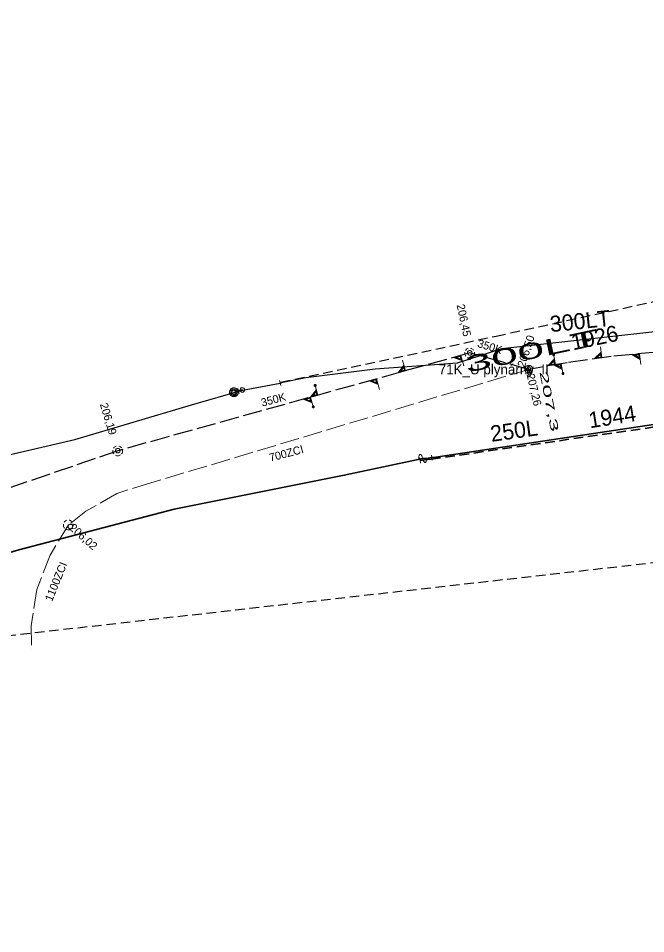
# Model space of a CAD drawing. Extents: x -740786 to -740000, y -1046854 to -1046100.
# Drawn here: x -740571.3 to -740508.6, y -1046832.5 to -1046741 of the extents above; entities that cross this region are included whole.
import ezdxf

# ---------------------------------------------------------------- set-up
doc = ezdxf.new("R2010")
doc.units = 0
doc.header["$LTSCALE"] = 0.32
doc.linetypes.add('LONG_DASHED', pattern=[7.5, 6, -1.5])
doc.linetypes.add('MEDIUM_DASHED', pattern=[4.5, 3, -1.5])
doc.layers.add('1', color=7, linetype='Continuous')
doc.layers.add('15', color=7, linetype='Continuous')
for name, color, linetype, lineweight in [('18', 7, 'Continuous', 13), ('20', 7, 'LONG_DASHED', 25), ('63', 7, 'MEDIUM_DASHED', 25), ('8', 7, 'Continuous', 13)]:
    doc.layers.add(name, color=color, linetype=linetype, lineweight=lineweight)

msp = doc.modelspace()

# ---------------------------------------------------------------- linework, layer by layer
at = {"layer": '18'}
for points in [[(-740526.323, -1046773.977), (-740526.394, -1046774.005), (-740526.461, -1046774.044), (-740526.521, -1046774.092), (-740526.572, -1046774.149), (-740526.596, -1046774.183)], [(-740525.782, -1046774.16), (-740525.832, -1046774.102), (-740525.89, -1046774.052), (-740525.955, -1046774.011), (-740526.026, -1046773.982), (-740526.075, -1046773.968)], [(-740513.109, -1046773.844), (-740512.959, -1046774.93), (-740513.722, -1046775.035), (-740513.039, -1046774.357)], [(-740526.76, -1046775.738), (-740527.054, -1046774.682), (-740527.797, -1046774.889), (-740526.899, -1046775.239)], [(-740526.98, -1046775.139), (-740527.091, -1046774.738), (-740527.636, -1046774.89), (-740526.98, -1046775.14)], [(-740527.048, -1046775.071), (-740527.126, -1046774.79), (-740527.483, -1046774.89), (-740527.047, -1046775.07)], [(-740526.668, -1046774.369), (-740526.674, -1046774.446), (-740526.669, -1046774.523), (-740526.652, -1046774.598), (-740526.623, -1046774.669), (-740526.583, -1046774.735), (-740526.567, -1046774.757)], [(-740526.41, -1046774.886), (-740526.34, -1046774.917), (-740526.265, -1046774.936), (-740526.189, -1046774.943), (-740526.112, -1046774.938), (-740526.037, -1046774.921), (-740525.965, -1046774.893), (-740525.905, -1046774.858)], [(-740525.787, -1046774.746), (-740525.746, -1046774.681), (-740525.715, -1046774.611), (-740525.696, -1046774.536), (-740525.688, -1046774.46), (-740525.693, -1046774.383), (-740525.699, -1046774.348)], [(-740517.798, -1046774.531), (-740517.609, -1046775.61), (-740518.368, -1046775.742), (-740517.709, -1046775.041)], [(-740513.072, -1046774.481), (-740513.015, -1046774.893), (-740513.576, -1046774.971), (-740513.072, -1046774.48)], [(-740513.107, -1046774.571), (-740513.067, -1046774.859), (-740513.436, -1046774.91), (-740513.106, -1046774.571)], [(-740509.079, -1046775.608), (-740509.187, -1046774.517), (-740509.954, -1046774.593), (-740509.13, -1046775.093)], [(-740509.192, -1046774.98), (-740509.233, -1046774.566), (-740509.795, -1046774.622), (-740509.192, -1046774.981)], [(-740509.247, -1046774.901), (-740509.276, -1046774.612), (-740509.645, -1046774.648), (-740509.246, -1046774.901)], [(-740532.883, -1046775.168), (-740532.589, -1046776.224), (-740533.331, -1046776.43), (-740532.744, -1046775.667)], [(-740532.761, -1046775.794), (-740532.649, -1046776.195), (-740533.195, -1046776.347), (-740532.761, -1046775.793)], [(-740532.784, -1046775.888), (-740532.706, -1046776.168), (-740533.064, -1046776.268), (-740532.783, -1046775.887)], [(-740517.738, -1046775.165), (-740517.666, -1046775.575), (-740518.224, -1046775.673), (-740517.738, -1046775.164)], [(-740517.77, -1046775.256), (-740517.719, -1046775.544), (-740518.086, -1046775.608), (-740517.769, -1046775.256)], [(-740516.831, -1046776.592), (-740517.019, -1046775.513), (-740517.779, -1046775.646), (-740516.92, -1046776.083)], [(-740516.99, -1046775.974), (-740517.062, -1046775.564), (-740517.62, -1046775.662), (-740516.99, -1046775.976)], [(-740517.051, -1046775.9), (-740517.101, -1046775.613), (-740517.467, -1046775.677), (-740517.05, -1046775.9)], [(-740541.641, -1046777.599), (-740541.348, -1046778.654), (-740542.09, -1046778.86), (-740541.503, -1046778.097)], [(-740535.19, -1046778.082), (-740535.484, -1046777.026), (-740536.227, -1046777.233), (-740535.329, -1046777.583)], [(-740535.41, -1046777.483), (-740535.521, -1046777.082), (-740536.066, -1046777.234), (-740535.41, -1046777.484)], [(-740535.478, -1046777.415), (-740535.556, -1046777.134), (-740535.913, -1046777.234), (-740535.477, -1046777.414)], [(-740541.519, -1046778.224), (-740541.408, -1046778.625), (-740541.953, -1046778.776), (-740541.519, -1046778.223)], [(-740541.542, -1046778.318), (-740541.464, -1046778.599), (-740541.822, -1046778.699), (-740541.541, -1046778.317)], [(-740541.787, -1046779.919), (-740542.08, -1046778.864), (-740542.823, -1046779.071), (-740541.925, -1046779.421)], [(-740542.006, -1046779.32), (-740542.118, -1046778.919), (-740542.663, -1046779.071), (-740542.006, -1046779.322)], [(-740542.074, -1046779.253), (-740542.152, -1046778.971), (-740542.509, -1046779.071), (-740542.073, -1046779.252)], [(-740561.848, -1046784.149), (-740561.853, -1046784.226), (-740561.848, -1046784.303), (-740561.831, -1046784.378), (-740561.803, -1046784.449), (-740561.762, -1046784.515), (-740561.747, -1046784.537)], [(-740561.503, -1046783.757), (-740561.574, -1046783.785), (-740561.641, -1046783.824), (-740561.701, -1046783.872), (-740561.752, -1046783.929), (-740561.776, -1046783.963)], [(-740560.962, -1046783.94), (-740561.012, -1046783.882), (-740561.07, -1046783.832), (-740561.135, -1046783.791), (-740561.206, -1046783.762), (-740561.255, -1046783.748)], [(-740560.967, -1046784.526), (-740560.926, -1046784.461), (-740560.895, -1046784.391), (-740560.875, -1046784.316), (-740560.868, -1046784.24), (-740560.873, -1046784.163), (-740560.879, -1046784.128)], [(-740561.59, -1046784.666), (-740561.52, -1046784.697), (-740561.445, -1046784.716), (-740561.369, -1046784.723), (-740561.292, -1046784.718), (-740561.217, -1046784.701), (-740561.145, -1046784.673), (-740561.085, -1046784.638)], [(-740566.442, -1046791.167), (-740566.513, -1046791.195), (-740566.58, -1046791.234), (-740566.64, -1046791.282), (-740566.691, -1046791.339), (-740566.715, -1046791.373)], [(-740565.901, -1046791.35), (-740565.951, -1046791.292), (-740566.009, -1046791.242), (-740566.074, -1046791.201), (-740566.145, -1046791.172), (-740566.194, -1046791.158)], [(-740566.787, -1046791.559), (-740566.793, -1046791.636), (-740566.788, -1046791.713), (-740566.771, -1046791.788), (-740566.742, -1046791.859), (-740566.701, -1046791.925), (-740566.686, -1046791.947)], [(-740566.529, -1046792.076), (-740566.459, -1046792.107), (-740566.384, -1046792.126), (-740566.308, -1046792.133), (-740566.231, -1046792.128), (-740566.156, -1046792.111), (-740566.084, -1046792.083), (-740566.024, -1046792.048)], [(-740565.906, -1046791.936), (-740565.865, -1046791.871), (-740565.834, -1046791.801), (-740565.815, -1046791.726), (-740565.807, -1046791.65), (-740565.812, -1046791.573), (-740565.818, -1046791.538)]]:
    msp.add_lwpolyline(points, dxfattribs=at)
for points in [[(-740525.939, -1046774.429), (-740525.945, -1046774.377), (-740525.963, -1046774.327), (-740525.991, -1046774.283), (-740526.029, -1046774.246), (-740526.074, -1046774.219), (-740526.124, -1046774.203), (-740526.176, -1046774.198), (-740526.228, -1046774.205), (-740526.277, -1046774.224), (-740526.321, -1046774.254), (-740526.356, -1046774.293), (-740526.382, -1046774.338), (-740526.397, -1046774.389), (-740526.4, -1046774.441), (-740526.392, -1046774.493), (-740526.371, -1046774.541), (-740526.341, -1046774.584), (-740526.301, -1046774.619), (-740526.255, -1046774.643), (-740526.204, -1046774.657), (-740526.152, -1046774.659), (-740526.1, -1046774.649), (-740526.052, -1046774.627), (-740526.01, -1046774.595), (-740525.977, -1046774.555), (-740525.953, -1046774.508), (-740525.941, -1046774.457)], [(-740517.874, -1046774.64), (-740517.863, -1046774.671), (-740517.841, -1046774.697), (-740517.812, -1046774.713), (-740517.778, -1046774.718), (-740517.746, -1046774.711), (-740517.718, -1046774.693), (-740517.697, -1046774.666), (-740517.687, -1046774.634), (-740517.69, -1046774.601), (-740517.704, -1046774.571), (-740517.727, -1046774.546), (-740517.758, -1046774.532), (-740517.791, -1046774.53), (-740517.824, -1046774.539), (-740517.851, -1046774.559), (-740517.868, -1046774.587), (-740517.876, -1046774.62)], [(-740517.847, -1046774.636), (-740517.837, -1046774.663), (-740517.817, -1046774.683), (-740517.79, -1046774.691), (-740517.762, -1046774.689), (-740517.737, -1046774.676), (-740517.721, -1046774.653), (-740517.714, -1046774.625), (-740517.72, -1046774.598), (-740517.736, -1046774.575), (-740517.761, -1046774.561), (-740517.789, -1046774.558), (-740517.816, -1046774.567), (-740517.837, -1046774.587), (-740517.848, -1046774.612)], [(-740519.882, -1046776.076), (-740519.888, -1046776.008), (-740519.906, -1046775.941), (-740519.935, -1046775.879), (-740519.974, -1046775.822), (-740520.023, -1046775.773), (-740520.079, -1046775.734), (-740520.141, -1046775.705), (-740520.208, -1046775.686), (-740520.276, -1046775.68), (-740520.345, -1046775.686), (-740520.412, -1046775.703), (-740520.474, -1046775.732), (-740520.531, -1046775.771), (-740520.58, -1046775.82), (-740520.62, -1046775.876), (-740520.649, -1046775.938), (-740520.668, -1046776.005), (-740520.674, -1046776.073), (-740520.669, -1046776.142), (-740520.651, -1046776.209), (-740520.623, -1046776.271), (-740520.584, -1046776.328), (-740520.536, -1046776.377), (-740520.48, -1046776.417), (-740520.417, -1046776.447), (-740520.351, -1046776.466), (-740520.283, -1046776.472), (-740520.214, -1046776.467), (-740520.147, -1046776.45), (-740520.084, -1046776.422), (-740520.027, -1046776.383), (-740519.978, -1046776.335), (-740519.938, -1046776.279), (-740519.908, -1046776.217), (-740519.889, -1046776.151), (-740519.882, -1046776.082)], [(-740520.267, -1046776.377), (-740520.231, -1046776.371), (-740520.196, -1046776.353), (-740520.164, -1046776.324), (-740520.136, -1046776.285), (-740520.114, -1046776.238), (-740520.098, -1046776.185), (-740520.089, -1046776.127), (-740520.087, -1046776.068), (-740520.093, -1046776.009), (-740520.106, -1046775.954), (-740520.126, -1046775.903), (-740520.151, -1046775.86), (-740520.182, -1046775.826), (-740520.216, -1046775.802), (-740520.252, -1046775.789), (-740520.289, -1046775.789), (-740520.325, -1046775.8), (-740520.359, -1046775.823), (-740520.389, -1046775.857), (-740520.414, -1046775.899), (-740520.434, -1046775.949), (-740520.447, -1046776.005), (-740520.453, -1046776.063), (-740520.451, -1046776.123), (-740520.442, -1046776.181), (-740520.426, -1046776.234), (-740520.404, -1046776.282), (-740520.376, -1046776.321), (-740520.344, -1046776.351), (-740520.309, -1046776.37), (-740520.272, -1046776.377)], [(-740519.946, -1046776.393), (-740519.953, -1046776.341), (-740519.97, -1046776.291), (-740519.999, -1046776.247), (-740520.037, -1046776.21), (-740520.081, -1046776.183), (-740520.132, -1046776.167), (-740520.184, -1046776.162), (-740520.235, -1046776.169), (-740520.284, -1046776.188), (-740520.328, -1046776.218), (-740520.364, -1046776.257), (-740520.39, -1046776.302), (-740520.404, -1046776.353), (-740520.407, -1046776.405), (-740520.399, -1046776.457), (-740520.379, -1046776.505), (-740520.348, -1046776.548), (-740520.309, -1046776.583), (-740520.262, -1046776.607), (-740520.212, -1046776.621), (-740520.159, -1046776.623), (-740520.108, -1046776.613), (-740520.059, -1046776.591), (-740520.017, -1046776.559), (-740519.985, -1046776.519), (-740519.961, -1046776.472), (-740519.948, -1046776.421)], [(-740516.941, -1046776.516), (-740516.929, -1046776.547), (-740516.907, -1046776.573), (-740516.878, -1046776.589), (-740516.845, -1046776.593), (-740516.812, -1046776.587), (-740516.784, -1046776.568), (-740516.763, -1046776.541), (-740516.754, -1046776.509), (-740516.756, -1046776.476), (-740516.77, -1046776.445), (-740516.793, -1046776.422), (-740516.823, -1046776.408), (-740516.857, -1046776.406), (-740516.889, -1046776.414), (-740516.916, -1046776.434), (-740516.935, -1046776.463), (-740516.942, -1046776.496)], [(-740516.914, -1046776.509), (-740516.904, -1046776.535), (-740516.883, -1046776.555), (-740516.857, -1046776.565), (-740516.828, -1046776.562), (-740516.804, -1046776.549), (-740516.786, -1046776.526), (-740516.78, -1046776.499), (-740516.786, -1046776.47), (-740516.803, -1046776.448), (-740516.827, -1046776.434), (-740516.856, -1046776.431), (-740516.882, -1046776.439), (-740516.903, -1046776.459), (-740516.914, -1046776.486)], [(-740541.706, -1046777.715), (-740541.692, -1046777.745), (-740541.668, -1046777.768), (-740541.637, -1046777.781), (-740541.603, -1046777.783), (-740541.572, -1046777.773), (-740541.546, -1046777.752), (-740541.528, -1046777.723), (-740541.521, -1046777.69), (-740541.527, -1046777.658), (-740541.543, -1046777.629), (-740541.569, -1046777.607), (-740541.601, -1046777.596), (-740541.634, -1046777.597), (-740541.666, -1046777.609), (-740541.691, -1046777.632), (-740541.706, -1046777.661), (-740541.71, -1046777.695)], [(-740541.68, -1046777.708), (-740541.667, -1046777.734), (-740541.645, -1046777.752), (-740541.618, -1046777.757), (-740541.59, -1046777.753), (-740541.566, -1046777.737), (-740541.552, -1046777.712), (-740541.549, -1046777.684), (-740541.557, -1046777.658), (-740541.576, -1046777.637), (-740541.602, -1046777.625), (-740541.63, -1046777.625), (-740541.656, -1046777.636), (-740541.674, -1046777.658), (-740541.683, -1046777.684)], [(-740541.903, -1046779.854), (-740541.889, -1046779.884), (-740541.865, -1046779.908), (-740541.834, -1046779.921), (-740541.801, -1046779.922), (-740541.769, -1046779.912), (-740541.743, -1046779.891), (-740541.725, -1046779.863), (-740541.718, -1046779.83), (-740541.723, -1046779.797), (-740541.741, -1046779.767), (-740541.766, -1046779.746), (-740541.797, -1046779.735), (-740541.831, -1046779.736), (-740541.862, -1046779.748), (-740541.887, -1046779.771), (-740541.903, -1046779.801), (-740541.907, -1046779.834)], [(-740541.878, -1046779.845), (-740541.865, -1046779.87), (-740541.842, -1046779.888), (-740541.815, -1046779.895), (-740541.787, -1046779.889), (-740541.764, -1046779.873), (-740541.749, -1046779.85), (-740541.745, -1046779.822), (-740541.754, -1046779.794), (-740541.773, -1046779.773), (-740541.798, -1046779.762), (-740541.828, -1046779.761), (-740541.852, -1046779.772), (-740541.871, -1046779.794), (-740541.88, -1046779.822)], [(-740561.119, -1046784.209), (-740561.125, -1046784.157), (-740561.142, -1046784.107), (-740561.171, -1046784.063), (-740561.209, -1046784.026), (-740561.254, -1046783.999), (-740561.304, -1046783.983), (-740561.356, -1046783.978), (-740561.407, -1046783.985), (-740561.456, -1046784.004), (-740561.5, -1046784.034), (-740561.536, -1046784.073), (-740561.562, -1046784.118), (-740561.576, -1046784.169), (-740561.58, -1046784.221), (-740561.571, -1046784.273), (-740561.551, -1046784.321), (-740561.521, -1046784.364), (-740561.481, -1046784.399), (-740561.434, -1046784.423), (-740561.384, -1046784.437), (-740561.331, -1046784.439), (-740561.28, -1046784.429), (-740561.232, -1046784.407), (-740561.19, -1046784.375), (-740561.157, -1046784.335), (-740561.133, -1046784.288), (-740561.12, -1046784.237)], [(-740565.862, -1046791.785), (-740565.868, -1046791.733), (-740565.886, -1046791.683), (-740565.914, -1046791.639), (-740565.952, -1046791.602), (-740565.997, -1046791.575), (-740566.047, -1046791.559), (-740566.099, -1046791.554), (-740566.151, -1046791.561), (-740566.2, -1046791.58), (-740566.244, -1046791.61), (-740566.279, -1046791.649), (-740566.305, -1046791.694), (-740566.32, -1046791.745), (-740566.323, -1046791.797), (-740566.315, -1046791.849), (-740566.294, -1046791.897), (-740566.264, -1046791.94), (-740566.224, -1046791.975), (-740566.178, -1046791.999), (-740566.127, -1046792.013), (-740566.075, -1046792.015), (-740566.023, -1046792.005), (-740565.975, -1046791.983), (-740565.933, -1046791.951), (-740565.9, -1046791.911), (-740565.876, -1046791.864), (-740565.864, -1046791.813)]]:
    msp.add_lwpolyline(points, close=True, dxfattribs=at)
at = {"layer": '20'}
for p, q in [((-740526.17, -1046774.44), (-740561.35, -1046784.22)), ((-740526.17, -1046774.44), (-740561.35, -1046784.22)), ((-740561.35, -1046784.22), (-740586.3, -1046792.8)), ((-740561.35, -1046784.22), (-740586.3, -1046792.8))]:
    msp.add_line(p, q, dxfattribs=at)
msp.add_lwpolyline([(-740464.809, -1046778.87), (-740468.967, -1046777.712), (-740473.69, -1046776.594), (-740478.593, -1046775.649), (-740482.353, -1046775.071), (-740486.829, -1046774.544), (-740491.064, -1046774.206), (-740495.107, -1046774.028), (-740499.182, -1046773.989), (-740503.074, -1046774.085), (-740507.47, -1046774.35), (-740512.021, -1046774.8), (-740516.44, -1046775.411), (-740520.27, -1046776.08), (-740526.17, -1046774.44)], dxfattribs=at)
msp.add_lwpolyline([(-740464.809, -1046778.87), (-740468.967, -1046777.712), (-740473.69, -1046776.594), (-740478.593, -1046775.649), (-740482.353, -1046775.071), (-740486.829, -1046774.544), (-740491.064, -1046774.206), (-740495.107, -1046774.028), (-740499.182, -1046773.989), (-740503.074, -1046774.085), (-740507.47, -1046774.35), (-740512.021, -1046774.8), (-740516.44, -1046775.411), (-740520.27, -1046776.08), (-740526.17, -1046774.44)], dxfattribs=at)
at = {"layer": '20', "lineweight": 13}
for points in [[(-740520.27, -1046776.08), (-740558.039, -1046787.43), (-740561.445, -1046788.486), (-740564.528, -1046790.272), (-740566.289, -1046791.63)], [(-740520.27, -1046776.08), (-740558.039, -1046787.43), (-740561.445, -1046788.486), (-740564.528, -1046790.272), (-740566.289, -1046791.63)], [(-740566.289, -1046791.63), (-740568.12, -1046794.648), (-740569.452, -1046798.083), (-740570.013, -1046801.725), (-740569.949, -1046804.13)], [(-740566.289, -1046791.63), (-740568.12, -1046794.648), (-740569.452, -1046798.083), (-740570.013, -1046801.725), (-740569.949, -1046804.13)]]:
    msp.add_lwpolyline(points, dxfattribs=at)
at = {"layer": '63'}
msp.add_lwpolyline([(-740455.336, -1046482.714), (-740468.522, -1046790.977), (-740468.522, -1046790.979), (-740468.523, -1046790.981), (-740468.524, -1046790.982), (-740468.525, -1046790.984), (-740468.527, -1046790.985), (-740468.529, -1046790.986), (-740468.531, -1046790.986), (-740589.04, -1046804.624), (-740589.042, -1046804.624), (-740589.044, -1046804.624), (-740589.046, -1046804.623), (-740589.047, -1046804.622), (-740589.049, -1046804.621), (-740589.05, -1046804.619), (-740589.05, -1046804.617), (-740589.051, -1046804.615), (-740596.533, -1046717.763), (-740626.694, -1046502.274)], dxfattribs=at)
at = {"layer": '8', "lineweight": 25}
for p, q in [((-740548.899, -1046778.149), (-740545.125, -1046777.451)), ((-740549.289, -1046778.24), (-740549.739, -1046778.38))]:
    msp.add_line(p, q, dxfattribs=at)
at = {"layer": '8'}
for p, q in [((-740545.188, -1046777.199), (-740545.062, -1046777.7)), ((-740549.367, -1046777.992), (-740549.21, -1046778.485)), ((-740531.098, -1046785.447), (-740531.159, -1046784.934)), ((-740530, -1046784.645), (-740529.915, -1046785.156))]:
    msp.add_line(p, q, dxfattribs=at)
at = {"layer": '8', "linetype": 'MEDIUM_DASHED', "lineweight": 25}
msp.add_lwpolyline([(-740545.05, -1046777.37), (-740523.519, -1046772.752), (-740507.612, -1046769.267), (-740490.756, -1046769.41), (-740488.377, -1046769.408), (-740462.339, -1046774.323), (-740444.309, -1046779.935), (-740440.26, -1046781.19), (-740426.241, -1046786.116), (-740418.958, -1046789.301), (-740410.476, -1046793.296), (-740406.559, -1046795.41)], dxfattribs=at)
at = {"layer": '8', "lineweight": 25}
for points in [[(-740545.125, -1046777.451), (-740544.864, -1046777.371), (-740542.545, -1046776.91), (-740535.611, -1046776.028), (-740527.396, -1046775.438), (-740522.967, -1046773.997), (-740507.359, -1046772.265), (-740488.394, -1046771.822), (-740486.079, -1046771.964)], [(-740602.17, -1046791.99), (-740594.85, -1046789.86), (-740585.52, -1046787.11), (-740576.14, -1046785.51), (-740565.64, -1046783.08), (-740553.969, -1046779.61), (-740548.899, -1046778.149)], [(-740548.899, -1046778.149), (-740548.902, -1046778.138), (-740549.289, -1046778.24)]]:
    msp.add_lwpolyline(points, dxfattribs=at)
at = {"layer": '8'}
for points in [[(-740549.308, -1046778.368), (-740549.311, -1046778.323), (-740549.318, -1046778.278), (-740549.33, -1046778.233), (-740549.345, -1046778.191), (-740549.367, -1046778.15), (-740549.392, -1046778.111), (-740549.421, -1046778.076), (-740549.453, -1046778.043), (-740549.489, -1046778.015), (-740549.526, -1046777.99), (-740549.568, -1046777.969), (-740549.61, -1046777.952), (-740549.654, -1046777.94), (-740549.7, -1046777.933), (-740549.745, -1046777.931), (-740549.791, -1046777.933), (-740549.837, -1046777.94), (-740549.88, -1046777.952), (-740549.924, -1046777.969), (-740549.965, -1046777.99), (-740550.002, -1046778.015), (-740550.039, -1046778.043), (-740550.071, -1046778.076), (-740550.1, -1046778.111), (-740550.125, -1046778.15), (-740550.146, -1046778.191), (-740550.161, -1046778.233), (-740550.174, -1046778.278), (-740550.181, -1046778.323), (-740550.183, -1046778.369), (-740550.181, -1046778.414), (-740550.174, -1046778.459), (-740550.161, -1046778.504), (-740550.146, -1046778.546), (-740550.125, -1046778.587), (-740550.1, -1046778.626), (-740550.071, -1046778.661), (-740550.039, -1046778.694), (-740550.002, -1046778.722), (-740549.965, -1046778.747), (-740549.924, -1046778.768), (-740549.88, -1046778.785), (-740549.837, -1046778.796), (-740549.791, -1046778.804), (-740549.745, -1046778.806), (-740549.7, -1046778.804), (-740549.654, -1046778.796), (-740549.61, -1046778.785), (-740549.568, -1046778.768), (-740549.526, -1046778.747), (-740549.489, -1046778.722), (-740549.453, -1046778.694), (-740549.421, -1046778.661), (-740549.392, -1046778.626), (-740549.367, -1046778.587), (-740549.345, -1046778.546), (-740549.33, -1046778.504), (-740549.318, -1046778.459), (-740549.311, -1046778.414), (-740549.308, -1046778.369)], [(-740531.243, -1046784.982), (-740531.249, -1046784.91), (-740531.25, -1046784.841), (-740531.245, -1046784.778), (-740531.234, -1046784.722), (-740531.22, -1046784.674), (-740531.201, -1046784.635), (-740531.178, -1046784.607), (-740531.152, -1046784.59), (-740531.124, -1046784.585), (-740531.093, -1046784.592), (-740531.061, -1046784.609), (-740531.03, -1046784.639), (-740530.998, -1046784.679), (-740530.968, -1046784.728), (-740530.94, -1046784.785), (-740530.915, -1046784.849), (-740530.894, -1046784.919), (-740530.876, -1046784.99), (-740530.872, -1046785.011)], [(-740530.872, -1046785.008), (-740530.854, -1046785.077), (-740530.832, -1046785.143), (-740530.806, -1046785.204), (-740530.778, -1046785.259), (-740530.748, -1046785.305), (-740530.717, -1046785.342), (-740530.685, -1046785.368), (-740530.655, -1046785.384), (-740530.625, -1046785.387), (-740530.598, -1046785.379), (-740530.575, -1046785.36), (-740530.556, -1046785.33), (-740530.541, -1046785.29), (-740530.53, -1046785.239), (-740530.524, -1046785.183), (-740530.524, -1046785.12), (-740530.529, -1046785.052), (-740530.534, -1046785.022)]]:
    msp.add_lwpolyline(points, dxfattribs=at)
for points in [[(-740549.421, -1046778.376), (-740549.428, -1046778.315), (-740549.446, -1046778.255), (-740549.475, -1046778.2), (-740549.514, -1046778.152), (-740549.561, -1046778.112), (-740549.615, -1046778.082), (-740549.674, -1046778.062), (-740549.735, -1046778.055), (-740549.798, -1046778.059), (-740549.857, -1046778.075), (-740549.913, -1046778.103), (-740549.963, -1046778.14), (-740550.004, -1046778.187), (-740550.036, -1046778.24), (-740550.056, -1046778.299), (-740550.066, -1046778.36), (-740550.063, -1046778.422), (-740550.048, -1046778.482), (-740550.022, -1046778.539), (-740549.985, -1046778.589), (-740549.94, -1046778.632), (-740549.887, -1046778.664), (-740549.83, -1046778.687), (-740549.769, -1046778.697), (-740549.706, -1046778.696), (-740549.646, -1046778.683), (-740549.588, -1046778.658), (-740549.538, -1046778.623), (-740549.494, -1046778.579), (-740549.46, -1046778.527), (-740549.436, -1046778.47), (-740549.424, -1046778.409)], [(-740549.536, -1046778.376), (-740549.541, -1046778.327), (-740549.558, -1046778.28), (-740549.587, -1046778.239), (-740549.625, -1046778.206), (-740549.669, -1046778.182), (-740549.717, -1046778.17), (-740549.767, -1046778.169), (-740549.815, -1046778.181), (-740549.86, -1046778.203), (-740549.897, -1046778.236), (-740549.926, -1046778.276), (-740549.946, -1046778.323), (-740549.953, -1046778.372), (-740549.948, -1046778.422), (-740549.931, -1046778.469), (-740549.904, -1046778.511), (-740549.867, -1046778.545), (-740549.823, -1046778.569), (-740549.776, -1046778.583), (-740549.725, -1046778.584), (-740549.676, -1046778.574), (-740549.632, -1046778.552), (-740549.593, -1046778.52), (-740549.563, -1046778.481), (-740549.544, -1046778.435), (-740549.536, -1046778.385)], [(-740548.668, -1046778.138), (-740548.674, -1046778.086), (-740548.691, -1046778.036), (-740548.72, -1046777.992), (-740548.758, -1046777.955), (-740548.803, -1046777.928), (-740548.853, -1046777.912), (-740548.905, -1046777.907), (-740548.956, -1046777.914), (-740549.005, -1046777.933), (-740549.049, -1046777.963), (-740549.085, -1046778.002), (-740549.111, -1046778.047), (-740549.125, -1046778.098), (-740549.129, -1046778.15), (-740549.12, -1046778.202), (-740549.1, -1046778.25), (-740549.07, -1046778.293), (-740549.03, -1046778.328), (-740548.983, -1046778.352), (-740548.933, -1046778.366), (-740548.88, -1046778.368), (-740548.829, -1046778.358), (-740548.781, -1046778.336), (-740548.739, -1046778.304), (-740548.706, -1046778.264), (-740548.682, -1046778.217), (-740548.669, -1046778.166)]]:
    msp.add_lwpolyline(points, close=True, dxfattribs=at)
at = {"layer": '8', "lineweight": 35}
for points in [[(-740529.958, -1046784.902), (-740529.552, -1046784.845), (-740506.48, -1046781.401), (-740488.414, -1046781.484), (-740473.581, -1046783.776), (-740456.01, -1046788.168), (-740450.964, -1046789.642), (-740447.322, -1046790.706), (-740429.436, -1046796.984), (-740404.93, -1046808.509), (-740390.532, -1046816.698), (-740374.355, -1046825.651)], [(-740530.873, -1046785.006), (-740538.71, -1046786.66), (-740555.71, -1046790.05), (-740571.23, -1046794.11), (-740594, -1046800.78), (-740599.92, -1046802.62), (-740628.26, -1046811.55), (-740632.43, -1046813.2), (-740638.649, -1046815.45), (-740640.18, -1046816.02)], [(-740530.03, -1046785.06), (-740530.708, -1046785.14), (-740531.129, -1046785.19)], [(-740530.873, -1046785.006), (-740530.327, -1046784.963), (-740529.958, -1046784.902)]]:
    msp.add_lwpolyline(points, dxfattribs=at)
at = {"layer": '8', "linetype": 'MEDIUM_DASHED', "lineweight": 35}
msp.add_lwpolyline([(-740530.03, -1046785.06), (-740506.197, -1046781.624), (-740492.614, -1046781.683), (-740480.958, -1046783.167), (-740461.337, -1046787.473), (-740450.943, -1046790.142), (-740447.603, -1046790.999), (-740434.64, -1046795.39), (-740429.405, -1046797.359), (-740416.811, -1046803.079), (-740374.397, -1046826.222), (-740362.605, -1046832.504)], dxfattribs=at)

# ---------------------------------------------------------------- texts
at = {"layer": '1'}
for s, rotation, p in [('206,45', 282, (-740527.483, -1046769.655)), ('350K', 343, (-740525.462, -1046773.823)), ('206,50', 72, (-740520.676, -1046775.935)), ('207,26', 283, (-740520.491, -1046776.615)), ('350K', 15, (-740546.908, -1046779.816)), ('206,19', 287, (-740563.15, -1046779.579)), ('700ZCI', 15, (-740546.097, -1046785.323)), ('206,02', 318, (-740566.265, -1046792.019)), ('1100ZCI ', 68, (-740567.923, -1046799.351))]:
    msp.add_text(s, height=0.8, rotation=rotation, dxfattribs=at).set_placement(p)
at = {"layer": '1', "width": 2.3}
msp.add_text('207,3 ', height=0.8, rotation=281, dxfattribs=at).set_placement((-740519.207, -1046776.334))
at = {"layer": '15'}
for s, rotation, p in [('300LT ', 6, (-740518.076, -1046772.363)), ('1926', 12, (-740515.852, -1046774.185)), ('1944', 9, (-740514.157, -1046781.973)), ('250L', 8, (-740523.99, -1046783.329))]:
    msp.add_text(s, height=1.6, rotation=rotation, dxfattribs=at).set_placement(p)
at = {"layer": '15', "width": 2.25}
msp.add_text('300LT ', height=1.6, rotation=12, dxfattribs=at).set_placement((-740526.459, -1046776.424))
at = {"layer": '18'}
msp.add_text('71K_U plynárny  II', height=1, dxfattribs=at).set_placement((-740529.27, -1046776.58))

doc.saveas('drawing.dxf')
